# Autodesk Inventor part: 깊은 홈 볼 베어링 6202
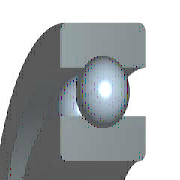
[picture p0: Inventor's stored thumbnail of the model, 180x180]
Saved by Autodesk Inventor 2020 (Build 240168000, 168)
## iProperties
IsCustomPart: 1
Created: 2012-02
Part Number: 깊은 홈 볼 베어링 6202
Material: 강철, 연강
Description: 깊은 그루부 볼 베어링
Document SubType Name: Modeling
Standard: JIS B 1521
Designer: mdu-01
Standards Organization: JIS
Language: ko-KR
Size Designation: 6202 15x35x11
Categories: <MemberInstance><Categories><Category DisplayName="샤프트 부품" InternalName="7f7aeb1f-a693-4053-b835-cee3144e0d98" Mnemonic="SHFT"><Category DisplayName="베어링" Inter
Density: 1 g/cm^3
Appearance: 강철(1)
Author: mdu-01
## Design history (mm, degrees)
sketch "스케치" dims "d0" = 5.2 (= -0.26 x WD + 0.26 x BD)
  geometry: L1 (2.9, 12.5)-(8.1, 12.5); L2 (5.5, 12.5)-(5.5, 9.9); L3 (5.5, 12.5)-(5.5, 15.1); L4 (3.568, 10.76)-(0, 10.76); L5 (0, 7.5)-(11, 7.5); L6 (3.568, 14.24)-(0, 14.24); L7 (0, 17.5)-(11, 17.5); L8 (11, 7.5)-(11, 10.76); L9 (7.432, 10.76)-(11, 10.76); L10 (7.432, 14.24)-(11, 14.24); L11 (11, 17.5)-(11, 14.24); L12 (-1.4, 0)-(8.4, 0) reference; L13 (0, -0.3)-(0, 5.3) reference
  constraints: 22 end point, 4 point on line, 2 collinear, 2 perpendicular, 2 symmetric about line, 1 midpoint, 1 parallel, 14 other
  dimensions: "d9" = 15 diameter of L5 L12 (= WD); "d11" = 35 diameter of L7 L12 (= BD); "d12" = 11 distance between parallel lines of L8 L13 (= KB); "d13" = 21.52 diameter of L9 L12 (= 0.326 x BD + 0.674 x WD)
revolve "본체" stored, may be unused: angle "d6" = 90 deg
revolve "볼" stored, may be unused: angle "d7" = 90 deg
pattern_circular "IDS_ARRAYBALL[SIMPL:T]" dims angle "d3" = 360 deg
body "Solid1"
fillet "모깎기1" dims "d1" = 0.6 (= KRS)
other parameters: "WD" = 15 [user parameter; used in 5 equation terms], "BD" = 35 [user parameter; used in 5 equation terms], "KB" = 11 [user parameter; used in 1 equation term], "KRS" = 0.6 [user parameter; used in 1 equation term], "d4" = 0, "d5" = 0, "d8" = 0, "d14" = 0, "d15" = 0, "BBA" = 0 [user parameter], "BC0" = 3750000 [user parameter], "BC" = 7800000 [user parameter], "BR" = 17.5 (= 0.5 x BD) [user parameter], "WR" = 7.5 (= 0.5 x WD) [user parameter]
